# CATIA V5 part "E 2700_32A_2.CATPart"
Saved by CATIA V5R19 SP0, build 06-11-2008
Definition: E 2700_32A_2
Nomenclature: E 2700_32A_2
Description: PART-E 2700_32A_2-DESC
Material "Plastic": density 1200 kg/m3, Young's modulus 2.2e+09 Pa, Poisson ratio 0.38, thermal expansion 6.84e-05 1/K
Bounding box of the stored display mesh (mm): x -36.2 to 36.2, y -35.4 to -12.6, z -11.5 to 18.6
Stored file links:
  G:\UTB\Kombinované\Bakalářská práce\Catia\FORMA\E 2700_32A_2.CATPart
  D:\Aplikace\CATIA\Nová složka\win_b64\startup\materials\Catalog.CATMaterial
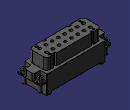
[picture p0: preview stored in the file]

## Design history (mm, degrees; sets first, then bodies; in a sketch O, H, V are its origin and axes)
Body1 "E 2700_32A" (main body)
  Solid1: solid without history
